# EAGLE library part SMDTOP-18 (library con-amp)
AMP connector
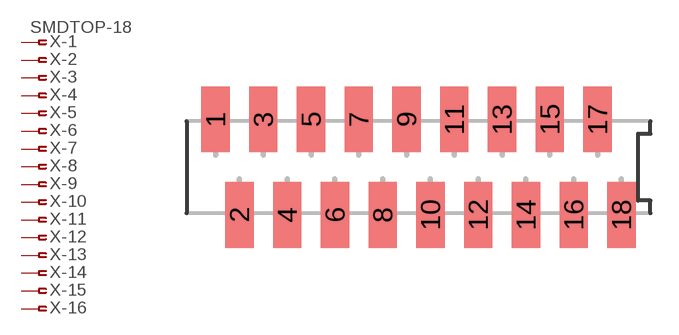
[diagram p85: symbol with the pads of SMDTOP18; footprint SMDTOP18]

Designator prefix X; gates -1=PIN-FV -2=PIN-F -3=PIN-F -4=PIN-F -5=PIN-F -6=PIN-F -7=PIN-F -8=PIN-F -9=PIN-F -10=PIN-F -11=PIN-F -12=PIN-F -13=PIN-F -14=PIN-F -15=PIN-F -16=PIN-F -17=PIN-F -18=PIN-F

## SMDTOP-18 (OC_FARNELL: unknown; OC_NEWARK: unknown)  [SMDTOP18]
1  -1:1  pas
2  -2:1  pas
3  -3:1  pas
4  -4:1  pas
5  -5:1  pas
6  -6:1  pas
7  -7:1  pas
8  -8:1  pas
9  -9:1  pas
10  -10:1  pas
11  -11:1  pas
12  -12:1  pas
13  -13:1  pas
14  -14:1  pas
15  -15:1  pas
16  -16:1  pas
17  -17:1  pas
18  -18:1  pas

## Footprint SMDTOP18 (pad centres in mm)
AMP connector
smd 1.5 x 3.5: 1 -10.795,2.54; 2 -9.525,-2.54; 3 -8.255,2.54; 4 -6.985,-2.54; 5 -5.715,2.54; 6 -4.445,-2.54; 7 -3.175,2.54; 8 -1.905,-2.54; 9 -0.635,2.54; 10 0.635,-2.54; 11 1.905,2.54; 12 3.175,-2.54; 13 4.445,2.54; 14 5.715,-2.54; 15 6.985,2.54; 16 8.255,-2.54; 17 9.525,2.54; 18 10.795,-2.54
